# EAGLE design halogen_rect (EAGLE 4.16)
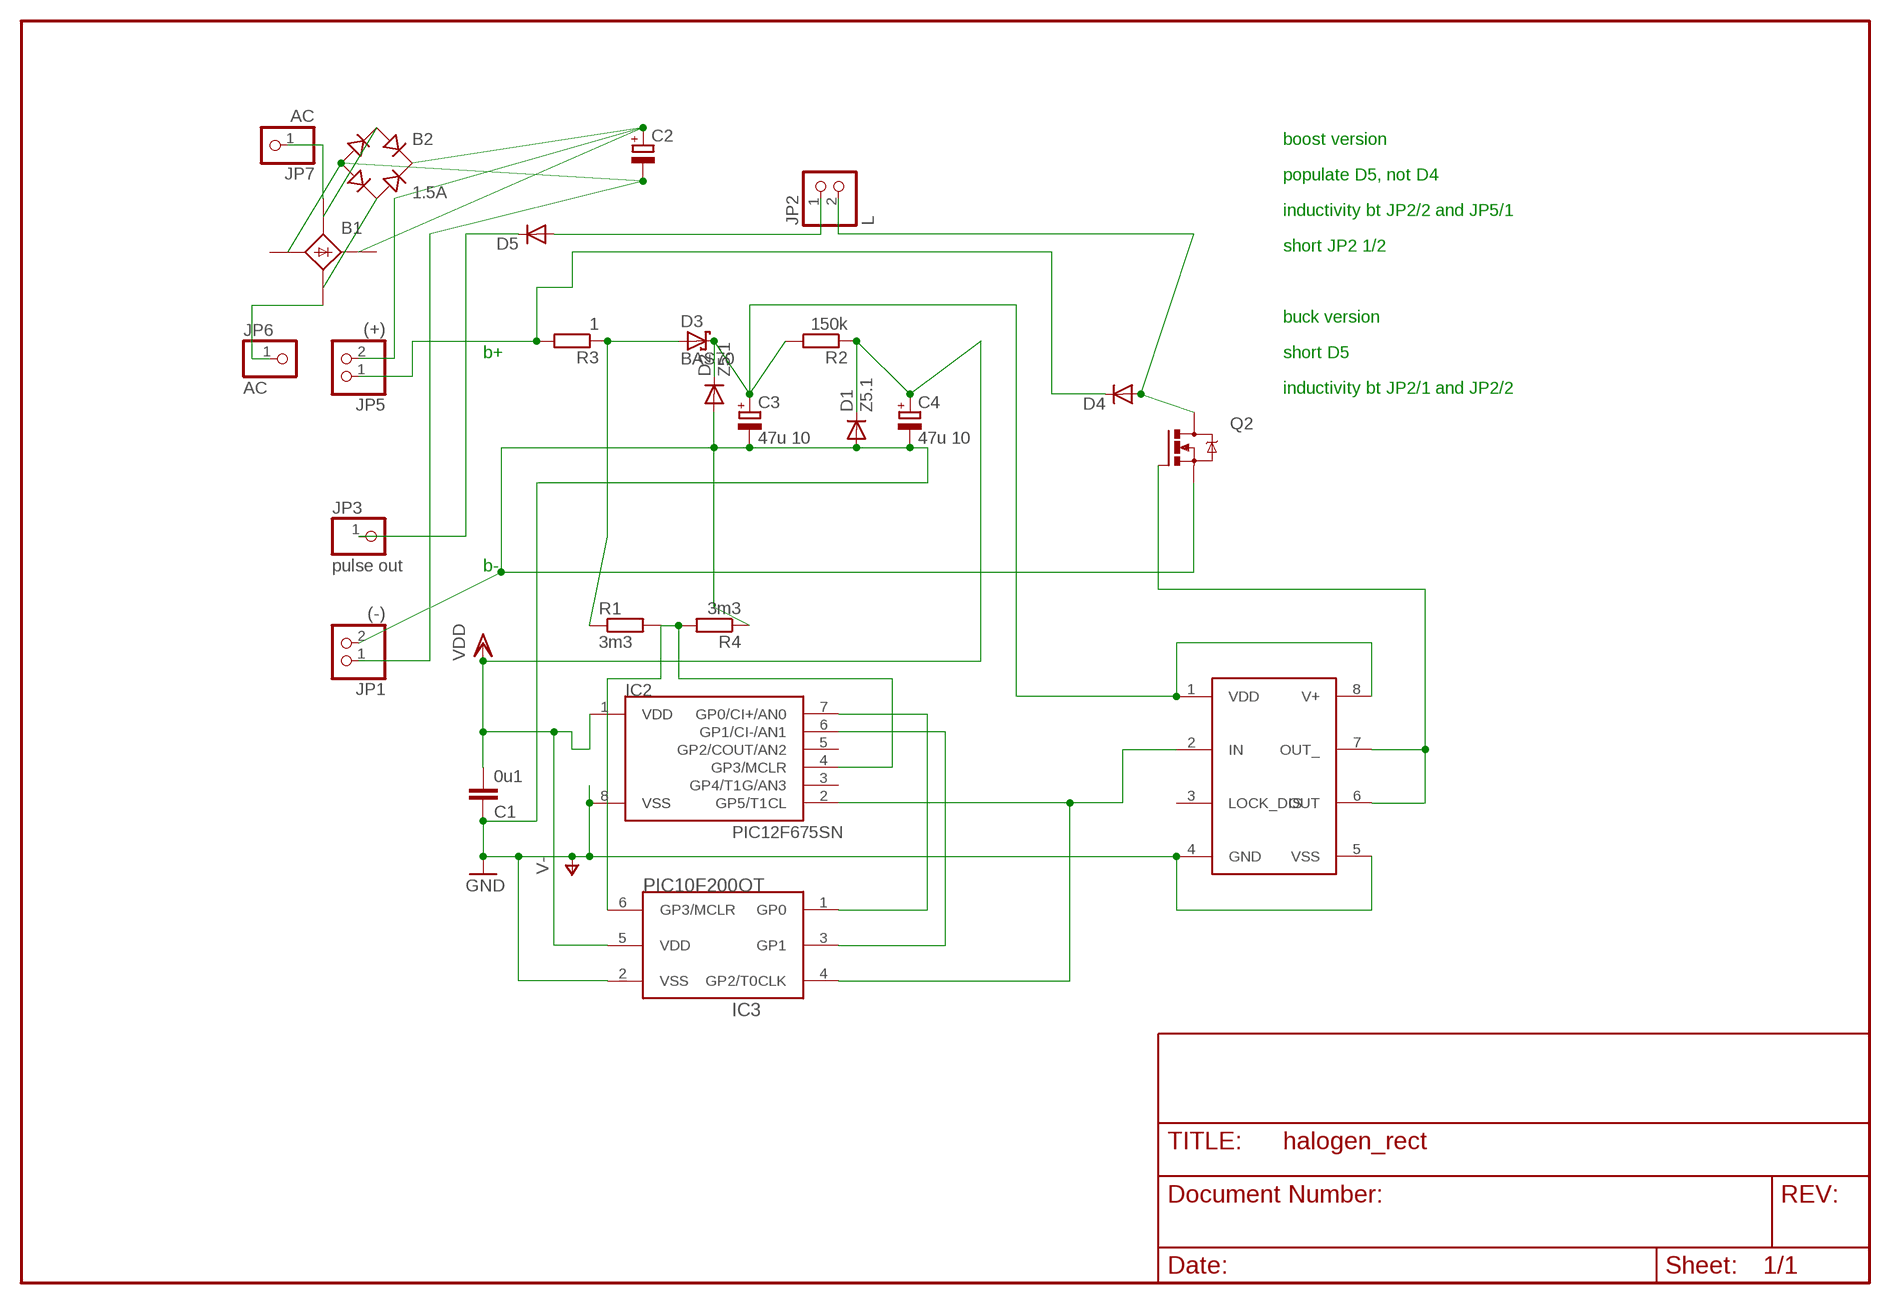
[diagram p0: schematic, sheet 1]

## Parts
B1  B25A-  [B25A-]
B2  1.5A  RECTIFIER-RB1A  [RB1A]
C1  0u1  C-EUC1206  [C1206]
C2  CPOL-EUE7.5-18  [E7,5-18]
C3  47u 10  CPOL-EUSMCD  [SMC_D]
C4  47u 10  CPOL-EUSMCD  [SMC_D]
D1  Z5.1  DIODE-MINIMELF  [MINIMELF]
D2  Z5.1  DIODE-MINIMELF  [MINIMELF]
D3  BAS70  [SOT23]
D4  DIODE-MELF-MLL41  [MELF-MLL41]
D5  DIODE-MELF-MLL41  [MELF-MLL41]
IC1  TC4432X  [SO-08]
IC2  PIC12F675SN  [SO-08]
IC3  PIC10F200OT  [SOT23-6]
JP1  (-)  PINHD-1X2  [1X02]
JP2  L  PINHD-1X2  [1X02]
JP3  pulse out  PINHD-1X1  [1X01]
JP5  (+)  PINHD-1X2  [1X02]
JP6  AC  PINHD-1X1  [1X01]
JP7  AC  PINHD-1X1  [1X01]
Q2  IRF540  [TO220BV]
R1  3m3  R-EU_R1206  [R1206]
R2  150k  R-EU_R1206  [R1206]
R3  1  R-EU_R1206  [R1206]
R4  3m3  R-EU_R1206  [R1206]

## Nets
N$1: D4.C JP5.1 R3.2
N$2: B1.AC1-(AC1) JP7.1
N$3: B1.AC2-(AC2) JP6.1
N$4: C3.+ D2.C D3.3(C) IC1.1(VDD) IC1.8(V+) R2.2
N$5: D5.A JP2.1
N$6: D3.1(A) R1.1 R3.1
N$7: IC1.6(OUT) IC1.7(OUT_) Q2.G
N$8: B1.AC1 B2.AC1
N$9: D4.A JP2.2 Q2.D
N$10: B1.+ B2.+ C2.+ JP5.2
N$11: B1.AC2 B2.AC2
N$12: IC2.4(GP3/MCLR) IC3.6(GP3/MCLR) R1.2 R4.2
N$13: B1.- B2.- C2.- JP1.1
N$14: IC1.2(IN) IC2.2(GP5/T1CL) IC3.4(GP2/T0CLK)
N$15: IC2.7(GP0/CI+/AN0) IC3.1(GP0)
N$16: IC2.6(GP1/CI-/AN1) IC3.3(GP1)
N$24: D5.C JP3.1
V-: C1.1 C3.- C4.- D1.A D2.A IC1.4(GND) IC1.5(VSS) IC2.8(VSS) IC3.2(VSS) JP1.2 Q2.S R4.1 ; supply symbol labelled GND
VDD: C1.2 C4.+ D1.C IC2.1(VDD) IC3.5(VDD) R2.1
Unconnected: B1.+1(+) B1.-1(-) IC1.3(LOCK_DIS) IC2.3(GP4/T1G/AN3) IC2.5(GP2/COUT/AN2)

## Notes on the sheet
- boost version
- populate D5, not D4
- inductivity bt JP2/2 and JP5/1
- short JP2 1/2
- buck version
- b+ | short D5
- inductivity bt JP2/1 and JP2/2
- b-

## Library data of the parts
B1 = rectifier:B25A-: RECTIFIER 25-A bridge
B2 = rectifier:RECTIFIER-: Rectifier
C1 = rcl:C-EU: CAPACITOR, European symbol
C2-C4 = rcl:CPOL-EU: POLARIZED CAPACITOR, European symbol
D1 D2 D4 D5 = diode:DIODE-: DIODE
D3 = diode:BAS70: Silicon Schottky Diodes
IC1 = microchip:TC4432
IC2 = microchip-3:PIC12F6*: uPC nW 1k Program Flash memory 2x Timer Comparator 10b A/D converter/ 4xIN
IC3 = microchip-3:PIC10F20*: uPC nW 0,25/0,5k Program Flash memory
JP1 JP2 JP5 = pinhead:PINHD-1X2: PIN HEADER
JP3 JP6 JP7 = pinhead:PINHD-1X1: PIN HEADER
Q2 = transistor-power:IRF540: HEXFET Power MOSFET
R1-R4 = rcl:R-EU_: RESISTOR, European symbol

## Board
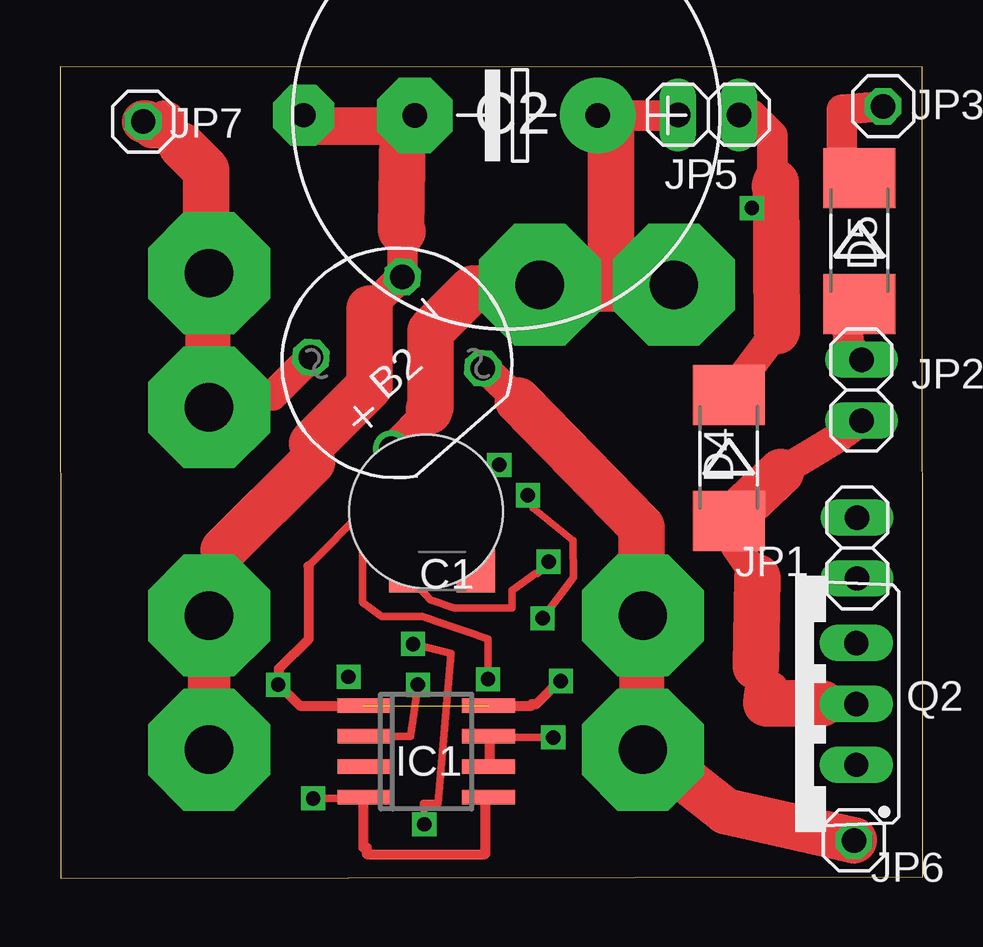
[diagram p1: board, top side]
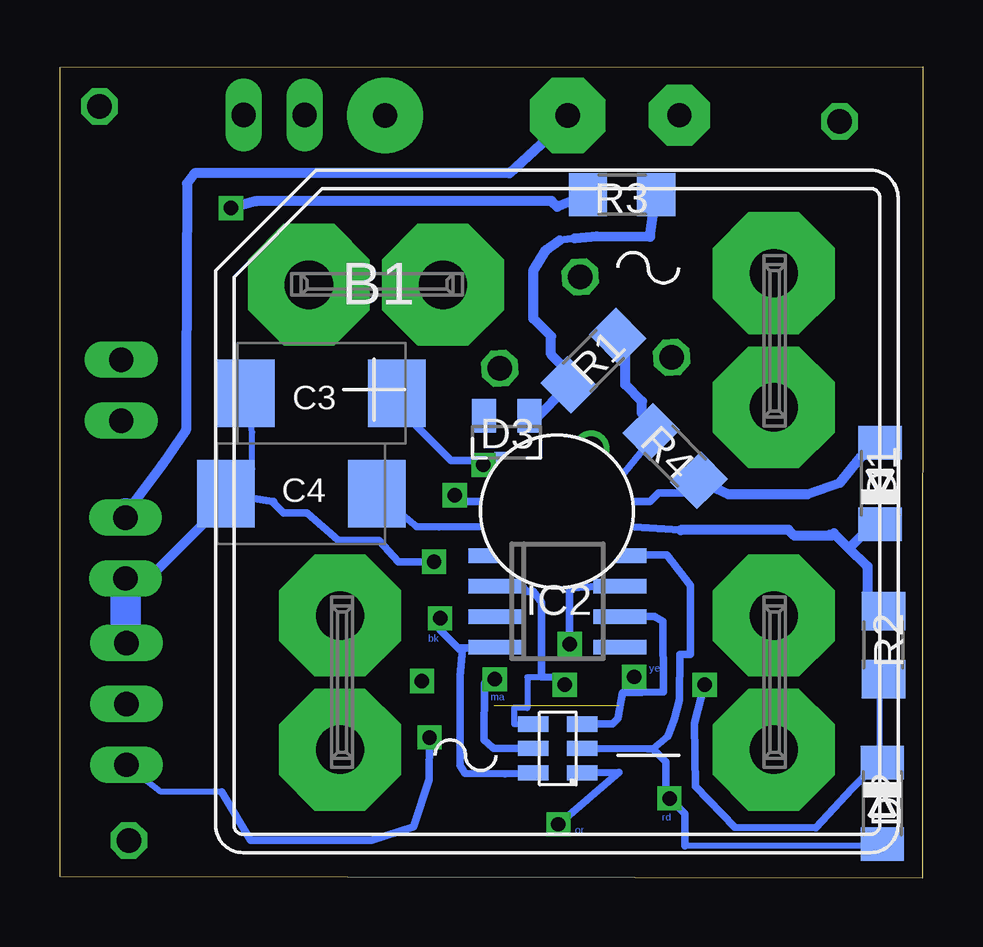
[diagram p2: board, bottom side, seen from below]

Size 35.97 x 33.82 mm. Coordinates in mm from the lower left corner, seen from the top.
Outline: 0.03,0 35.97,0.06 35.95,33.81 0,33.82 0.03,0
Copper layers (1*16): Top 0.035mm / dielectric 1.5mm / Bottom 0.035mm
Design rules "default": minimum track width 10mil, minimum drill 24mil, track to track 8mil, track to pad 8mil, pad to pad 8mil, via to via 8mil, smd to smd 8mil, copper to edge 40mil, drill to drill 8mil, minimum pad ring 10mil, minimum via ring 8mil, stop-mask expansion 4mil, vias tented up to drill 0mil, thermal gap 10mil

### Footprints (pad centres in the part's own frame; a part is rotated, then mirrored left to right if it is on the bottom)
B25A- = drill 2.007 pad 5.08 octagon: + -10.338,9.449; +1 -4.75,9.449; - 9.042,-4.343; -1 9.042,-9.931; AC1 9.042,4.343; AC1- 9.042,9.931; AC2 -9.042,-4.343; AC2- -9.042,-9.931 | hole 6.401: 0,0
RB1A = drill 1.016 round: + -2.54,2.54 | drill 1.016 octagon: - 2.54,-2.54; AC1 2.54,2.54; AC2 -2.54,-2.54
C1206 = smd 1.6 x 1.8: 1 -1.4,0; 2 1.4,0
E7,5-18 = drill 1.016 pad 3.15 round: + -3.81,0 | drill 1.016 pad 3.15 octagon: - 3.81,0
SMC_D = smd 2.4 x 2.8: + -3.15,0; - 3.15,0
MINIMELF = smd 1.4 x 1.8: A 1.7,0; C -1.7,0
SOT23 = smd 1 x 1.4: 1 -0.95,-1.1; 2 0.95,-1.1; 3 0,1.1
MELF-MLL41 = smd 2.5 x 3: A 2.625,0; C -2.625,0
SO-08 = smd 0.6 x 2.2: 1 -1.905,-2.6; 2 -0.635,-2.6; 3 0.635,-2.6; 4 1.905,-2.6; 5 1.905,2.6; 6 0.635,2.6; 7 -0.635,2.6; 8 -1.905,2.6
SOT23-6 = smd 0.635 x 1.27: 1 -1.016,-1.016; 2 0,-1.016; 3 1.016,-1.016; 4 1.016,1.016; 5 0,1.016; 6 -1.016,1.016
1X02 = drill 1.016 long: 1 -1.27,0; 2 1.27,0
1X01 = drill 1.016 octagon: 1 0,0
TO220BV = drill 1.016 long: D 0,-2.54; G -2.54,-2.54; S 2.54,-2.54
R1206 = smd 1.6 x 1.803: 1 -1.422,0; 2 1.422,0

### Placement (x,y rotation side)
B1  15.25,15.29 0 bottom
B2  14.05,21.48 131.3 top
C1  15.93,12.81 0 top
C2  18.61,31.8 180 top
C3  25.07,20.21 180 bottom
C4  25.91,16.02 180 bottom
D1  1.78,16.45 90 bottom
D2  1.69,3.12 270 bottom
D3  17.35,18.17 180 bottom
D4  27.88,17.51 270 top
D5  33.32,26.56 270 top
IC1  15.27,5.28 270 top
IC2  15.23,11.54 270 bottom
IC3  15.21,5.41 90 bottom
JP1  33.24,13.76 270 top
JP2  33.41,20.34 270 top
JP3  34.32,32.18 0 top
JP5  27.04,31.82 180 top
JP6  33.1,1.57 0 top
JP7  3.47,31.54 0 top
Q2  30.66,7.26 90 top
R1  13.73,21.57 44.9 bottom
R2  1.64,9.71 270 bottom
R3  12.54,28.49 180 bottom
R4  10.33,17.6 134.6 bottom

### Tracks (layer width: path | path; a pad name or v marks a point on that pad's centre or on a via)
N$1  (via drill 0.6)
  Top 0.305: 29.85,29 29.92,29 29.63,29 v28.84,27.93
  Top 0.406: 28.84,31.82 JP5.1 | 29.63,29 29.63,29.03 29.69,29.09
  Top 1.27: 29.88,22.8 D4.C | 28.84,31.82 29.69,30.97 29.69,29.09
  Top 1.93: 29.88,22.8 29.85,29 29.81,28.84
  Bottom 0.406: R3.2 15.23,27.99 15.47,28.23 27.8,28.21 v28.84,27.93
N$2
  Top 0.406: 4.37,31.54 4.58,31.33 4.58,30.87 4.89,30.56 5.05,30.56
  Top 1.27: 5.05,30.56 5.05,30.64
  Top 1.778: 4.37,31.54 4.37,31.34 4.33,31.3 3.86,31.3 3.62,31.54 JP7.1
  Top 1.93: B1.AC1- 6.16,25.17 6.1,25.17 6.1,29.52 5.05,30.56
N$3
  Top 1.778: B1.AC2- 24.29,5.6 | 24.29,5.6 24.29,10.43 24.19,10.54 24.19,5.7 24.29,5.6 | 24.29,5.6 24.52,5.37 24.52,5.32
  Top 1.93: JP6.1 27.76,2.78 24.52,5.32
N$4  (via drill 0.6)  (1 unrouted)
  Top 0.305: 10.36,12.9 10.35,13 10.85,13.49 13.59,16.28 17.44,17.09 v18.31,17.23
  Top 0.406: v9.09,8.06 9.13,8.06 | IC1.1 10.01,7.18 9.13,8.06 | 9.13,8.06 9.13,8.73 10.38,9.98 10.38,12.96 10.35,13 | IC1.8 19.66,7.18 19.66,7.26 19.86,7.26 20.82,8.21
  Bottom 0.254: D2.C 1.79,5.38 1.79,7.67 R2.2
  Bottom 0.305: v9.09,8.06 9.52,6.45 9.49,3.82 7.82,2.12 4.46,2.1 2.96,3.72 1.79,4.86 1.73,4.86 D2.C | 17.32,17.23 17.35,17.2 D3.3 | 17.32,17.23 v18.31,17.23 18.25,17.29 18.36,17.41 19.66,17.41 21.6,19.35 C3.+ | 17.32,17.23 17.28,17.27
N$5
  Top 1.27: D5.A 32.8,23.38 32.88,22.21 JP2.1
N$6
  Bottom 0.305: 14.57,20.72 14.72,20.57 R1.1 14.74,21.07 | D3.1 16.25,19.04 | 15.13,26.59 14.5,26.68
  Bottom 0.406: 16.25,19.04 14.72,20.57 | 14.74,21.07 15.49,21.83 15.49,22.59 16.23,23.32 16.23,25.32 15.7,26.18 15.13,26.59 | R3.1 11.37,26.74 13.59,26.75 14.5,26.68
N$7  (via drill 0.6)
  Top 0.305: IC1.7 17.9,5.87 v20.56,5.86
  Top 0.406: IC1.7 17.92,5.91 17.92,4.64 IC1.6
  Bottom 0.254: 29.22,3.6 31.76,3.6 Q2.G
  Bottom 0.305: v20.56,5.86 20.57,4.1 21.22,2.13 22.97,1.57 28.02,1.57 29.22,3.6
N$8
  Top 1.27: B2.AC1 8.87,20.12 6.01,20.12
  Top 1.778: 6.12,19.54 6.12,20.01 | 6.12,20.01 6.12,25.13 6.21,25.22 6.21,19.82 6.12,19.73 | 6.12,19.73 5.94,19.55 | 6.12,20.01 6.12,19.73
  Top 1.93: 6.12,19.31 6.12,19.54 B1.AC1 | 6.12,20.01 6.01,20.12
N$9
  Top 1.27: 31.75,7.28 Q2.D | 29.49,7.7 29.02,8.83 | D4.A 27.96,14.97 28.16,14.97 28.16,13.88 29.07,12.54 | 32.46,18.38 32.49,18.38 | 32.46,18.38 JP2.2 | 30.04,16.94 32.46,18.38
  Top 1.93: 31.75,7.28 29.45,7.28 29.49,7.7 | 29.02,8.83 29.07,12.54 | D4.A 30.04,16.94
N$10
  Top 0.406: JP5.2 25.9,31.82 25.9,31.78 25.9,31.76
  Top 1.016: 22.96,31.25 23.22,31.25 23.22,31.78
  Top 1.27: B2.+ 15.38,19.46 | 23.22,31.78 25.9,31.78
  Top 1.93: 15.38,19.46 15.38,19.57 15.46,19.64 15.46,22.8 17.22,24.57 22.96,24.57 | B1.+ 25.54,24.68 25.54,24.57 22.96,24.57 | C2.+ 22.96,31.25 22.96,24.57
N$11
  Top 1.27: 19.09,19.91 17.75,21.25 B2.AC2
  Top 1.93: 24.24,10.89 24.24,10.45 | B1.AC2 24.24,10.89 | 19.09,19.91 24.24,14.64 24.24,10.89
N$12  (via drill 0.6)
  Top 0.305: v19.51,15.96 19.71,15.44 21.39,14.08 21.4,12.53 v20.12,10.83
  Bottom 0.254: R4.2 11.7,19.35
  Bottom 0.305: IC3.6 17.41,4.35 19.09,4.36 19.29,4.69 19.29,8.41 19.23,9.1 19.18,9.55 19.3,9.61 | IC2.4 17.77,9.68 17.97,9.6 18.81,9.6 19.3,9.61 | R1.2 12.72,22.53 12.4,22.21 | R4.2 11.32,18.26 12.71,16.58 15.46,16.58 15.68,16.64 15.98,16.44 16.7,15.69 19.1,15.69 v19.51,15.96 | 19.3,9.61 19.3,9.53 20.12,10.35 v20.12,10.83
  Bottom 0.406: 11.7,19.35 11.7,19.87 12.4,20.57 12.4,22.21
N$13
  Top 0.406: 6.21,5.18 6.36,5.02 6.36,11.3 6.82,11.75 6.83,11.75
  Top 1.016: 14.28,31.07 10.2,31.07 10.2,31.62 14.74,31.62 14.74,31.8 C2.-
  Top 1.27: 14.28,26.95 B2.- 14.24,25.07 12.92,23.74 | 10.52,17.36 10.52,18.12 | 6.21,11.13 B1.- | 6.83,11.75 6.83,13.67
  Top 1.778: 6.21,5.18 6.21,11.13
  Top 1.93: C2.- 14.8,31.59 | 14.28,26.95 14.22,27.01 14.28,31.07 | 12.92,23.74 12.92,20.52 10.52,18.12 | 6.83,13.67 10.52,17.36
  Bottom 0.406: 33.24,15.2 31.71,17.23 30.71,18.69 30.7,20.78 30.67,28.96 30.35,29.38 17.23,29.38 14.6,31.8
  Bottom 1.27: 33.24,15.2 JP1.1 | 14.58,31.82 14.6,31.8 C2.-
N$14  (via drill 0.6)
  Top 0.305: IC1.2 12.67,5.9 14.6,5.9 v14.92,8.06
  Bottom 0.254: IC3.4 17.03,6.42 17.03,7.11 16.48,7.09 16.48,8.38 14.78,8.38
  Bottom 0.305: v14.92,8.06 14.78,8.38 15.9,8.39 15.89,11.49 16.22,11.96 16.5,11.96 16.75,12.21 17.86,12.21 IC2.2
N$15  (via drill 0.6)
  Top 0.305: v15.19,2.24 15.15,3.12 15.76,3.12 16.29,9.37 v14.72,9.76
  Bottom 0.305: IC3.1 12.67,4.41 v15.19,2.24 | IC2.7 13.02,12.17 14.72,12.1 v14.72,9.76
N$16
  Bottom 0.305: IC2.6 11.18,10.9 10.83,10.7 10.82,7.75 12.52,7.72 12.7,6.66 12.94,6.42 13.98,6.42 14,6.41 14.01,6.42 IC3.3
N$17  (via drill 0.6)
  other vias: 12.03,8.39
N$18  (via drill 1 pad 2.54)
  other vias: 10.15,31.81
N$19  (via drill 0.6)
  other vias: 20.88,8.21
N$24
  Top 1.27: JP3.1 32.59,32.02 32.59,28.83 D5.C
V-  (via drill 0.6)
  Top 0.305: IC1.4 12.61,3.32 v10.55,3.32 | v20.37,13.19 20.37,13.15 19.91,12.69 19.82,12.69 18.85,12 18.85,11.26 16.43,11.26 15.46,11.59 14.71,12.4 14.62,12.52 14.55,12.58 C1.1 15.2,13.52 16.04,14.36 v16.04,14.7
  Top 0.406: IC1.5 17.73,3.37 17.73,1 12.79,1 12.79,1.26 12.64,1.26 12.64,3.37 IC1.4
  Bottom 0.254: 9.92,1.34 2.55,1.34 D2.A | C4.- 27.95,17.06 27.95,18.59 C3.- | 2.55,17.57 D1.A
  Bottom 0.305: D2.A | 9.92,1.34 9.91,2.06 9.91,2.67 v10.55,3.32 | IC3.2 11.48,5.38 11.24,5.38 | v10.55,3.32 10.52,3.28 10.52,3.25 10.55,3.25 | 10.55,3.25 10.73,3.25 | IC2.8 12.67,13.39 | IC2.8 13,13.44 13.04,13.41 13.07,13.43 15.16,13.43 16.04,14.31 v16.04,14.7 16.04,14.98 16.1,15.04 15.67,15.48 15.61,15.48 15.19,15.9 13.14,15.9 12.94,15.69 11.38,15.69 11.02,16.05 9.82,16.05 R4.1 8.92,16.58 | IC2.8 12.6,13.47 10.67,13.47 9.69,12.2 9.69,9.33 10.13,9.33 10.13,7.42 10.35,6.64 10.62,5.9 11.24,5.38 | 27.1,15.7 27.05,15.69 | 27.1,15.7 C4.- | v20.37,13.19 21.86,13.19 22.67,14.08 24.35,14.08 25.67,15.22 26.64,15.22 27.1,15.68 27.1,15.7 | 11.24,5.38 10.71,4.85 10.71,3.4 10.55,3.25 | v10.55,3.32 10.55,3.25
  Bottom 0.406: 2.55,17.57 3.44,16.49 4.8,16.01 8.1,16.01 R4.1 | C4.- 29.06,15.7 32.17,12.59 33.3,12.59 33.4,12.49 | 33.4,12.49 33.45,12.44 | 33.4,12.49 JP1.2 | Q2.S 33.27,9.88 33.24,9.91
  Bottom 1.27: JP1.2 33.24,9.91
VDD  (via drill 0.6)
  Top 0.305: v14.3,14.79 15.13,15.83 17.23,16.24 17.72,15.35 v17.78,14.66 17.82,14.66 17.83,14.68 18,14.51 C1.2 | v17.84,8.29 17.84,9.98 15.09,10.9 13.4,10.9 12.62,11.5 12.62,13.9 14.29,14.92 | 14.29,14.92 14.34,14.92 | v14.3,14.79 14.29,14.92 | v14.31,14.79 14.33,14.8 | v14.3,14.79 v14.31,14.79 | v14.31,14.79 14.25,14.73
  Bottom 0.254: 2.55,14.27 D1.C | R2.1 2.3,11.73 | 2.3,13 2.31,12.99 | 3.82,14.37 3.82,14.27 | 5.6,14.52 5.6,14.51
  Bottom 0.305: 5.6,14.51 5.54,14.51 | 10.1,14.51 v14.3,14.79 | 17.73,13.44 17.7,13.42 | 17.73,13.44 IC2.1 17.83,13.82 17.77,13.88 17.77,14.55 17.82,14.6 | 17.73,13.44 17.75,13.47 v17.78,14.66 20.15,14.64 21.11,14.65 C4.+ | IC3.5 17.89,5.4 18.29,5.76 18.28,8.11 v17.84,8.29 | 3.7,14.37 3.82,14.37 3.9,14.37 | 2.31,12.99 2.25,12.92
  Bottom 0.406: 5.6,14.51 10.1,14.51 | 2.31,12.99 3.07,13.75 | 3.07,13.75 3.7,14.37 | 3.07,13.75 2.55,14.27 | 2.3,11.73 2.3,13 | 3.82,14.27 5.35,14.27 5.6,14.52

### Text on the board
Bottom: bk | ye | ma | rd | or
